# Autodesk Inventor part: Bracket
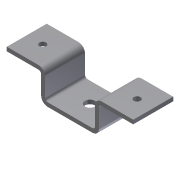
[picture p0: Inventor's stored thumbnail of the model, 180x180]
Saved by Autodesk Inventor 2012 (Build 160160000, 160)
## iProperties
Shininess: 64.0
Length Units: 11269
Angle Units: 11279
Time Units: 11290
Mass Units: 11283
Length Display Precision: 3
Angle Display Precision: 2
Compacted: True
Part Number: Bracket
Document SubType Name: Modeling
Created: 2003-01
Designer: Owner
Density: 1 g/cm^3
Material: Default
Density: 0.0
Volumn: 0.0
Area: 0.0
PropertySet Name: Model Information
Control State: 0
Master: False
Checked Out: False
Author: Owner
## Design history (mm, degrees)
node "Sketch1"
sketch "Sketch2"
  geometry: L1 (487.39, 112.858)-(199.89, 112.858); L2 (199.89, 112.858)-(199.89, -95.142); L3 (199.89, -95.142)-(-175.11, -95.142); L4 (-175.11, -95.142)-(-175.11, 112.858); L5 (-175.11, 112.858)-(-462.61, 112.858); L6 (-462.61, 82.858)-(-205.11, 82.858); L7 (-205.11, 82.858)-(-205.11, -125.142); L8 (-205.11, -125.142)-(229.89, -125.142); L9 (229.89, -125.142)-(229.89, 82.858); L10 (229.89, 82.858)-(487.39, 82.858); L11 (487.39, 112.858)-(487.39, 82.858); L12 (-462.61, 112.858)-(-462.61, 82.858)
  constraints: 24 end point, 5 parallel, 3 perpendicular, 2 collinear, 2 equal length, 1 horizontal, 4 other
  dimensions: "d0" = 375 distance between parallel lines of L4 L2; "d1" = 950 distance of L5.end L1.start; "d2" = 30 distance between parallel lines of L1 L10; "d3" = 238 distance between parallel lines of L5 L8
extrude "Extrusion1" new body sketch "Sketch2" stored distance "d4" = 300; taper "d5" = 0 deg
fillet "Fillet1" dims "d6" = 20
fillet "Fillet2" dims "d7" = 50
sketch "Sketch3"
  geometry: L1 (237.5, 300)-(0, 300) reference; L2 (0, 300)-(0, 0) reference; 1 further point
  dimensions: "d8" = 120 distance from line of L2 point (120, 150); "d9" = 150 distance from line of L1 point (120, 150)
hole "Hole1" sketch "Sketch3" at (120, 150) diameter "d10" = 50; stored, may be unused: countersink angle "d14" = 82 deg, drill point angle "d16" = 118 deg; dims "d11" = 6, "d12" = 4, "d13" = 2, "d15" = 8
pattern_linear "Rectangular Pattern1" dims "d19" = 710
sketch "Sketch4"
  geometry: L1 (0, -300)-(335, -300) reference; 1 further point
  dimensions: "d20" = 150 distance from line of L1 point (167.5, -150)
hole "Hole2" sketch "Sketch4" at (167.5, -150) diameter "d21" = 75; stored, may be unused: countersink angle "d25" = 82 deg, drill point angle "d27" = 118 deg; dims "d22" = 6, "d23" = 4, "d24" = 2, "d26" = 8
body "Solid1"
